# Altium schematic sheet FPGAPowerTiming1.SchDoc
size C
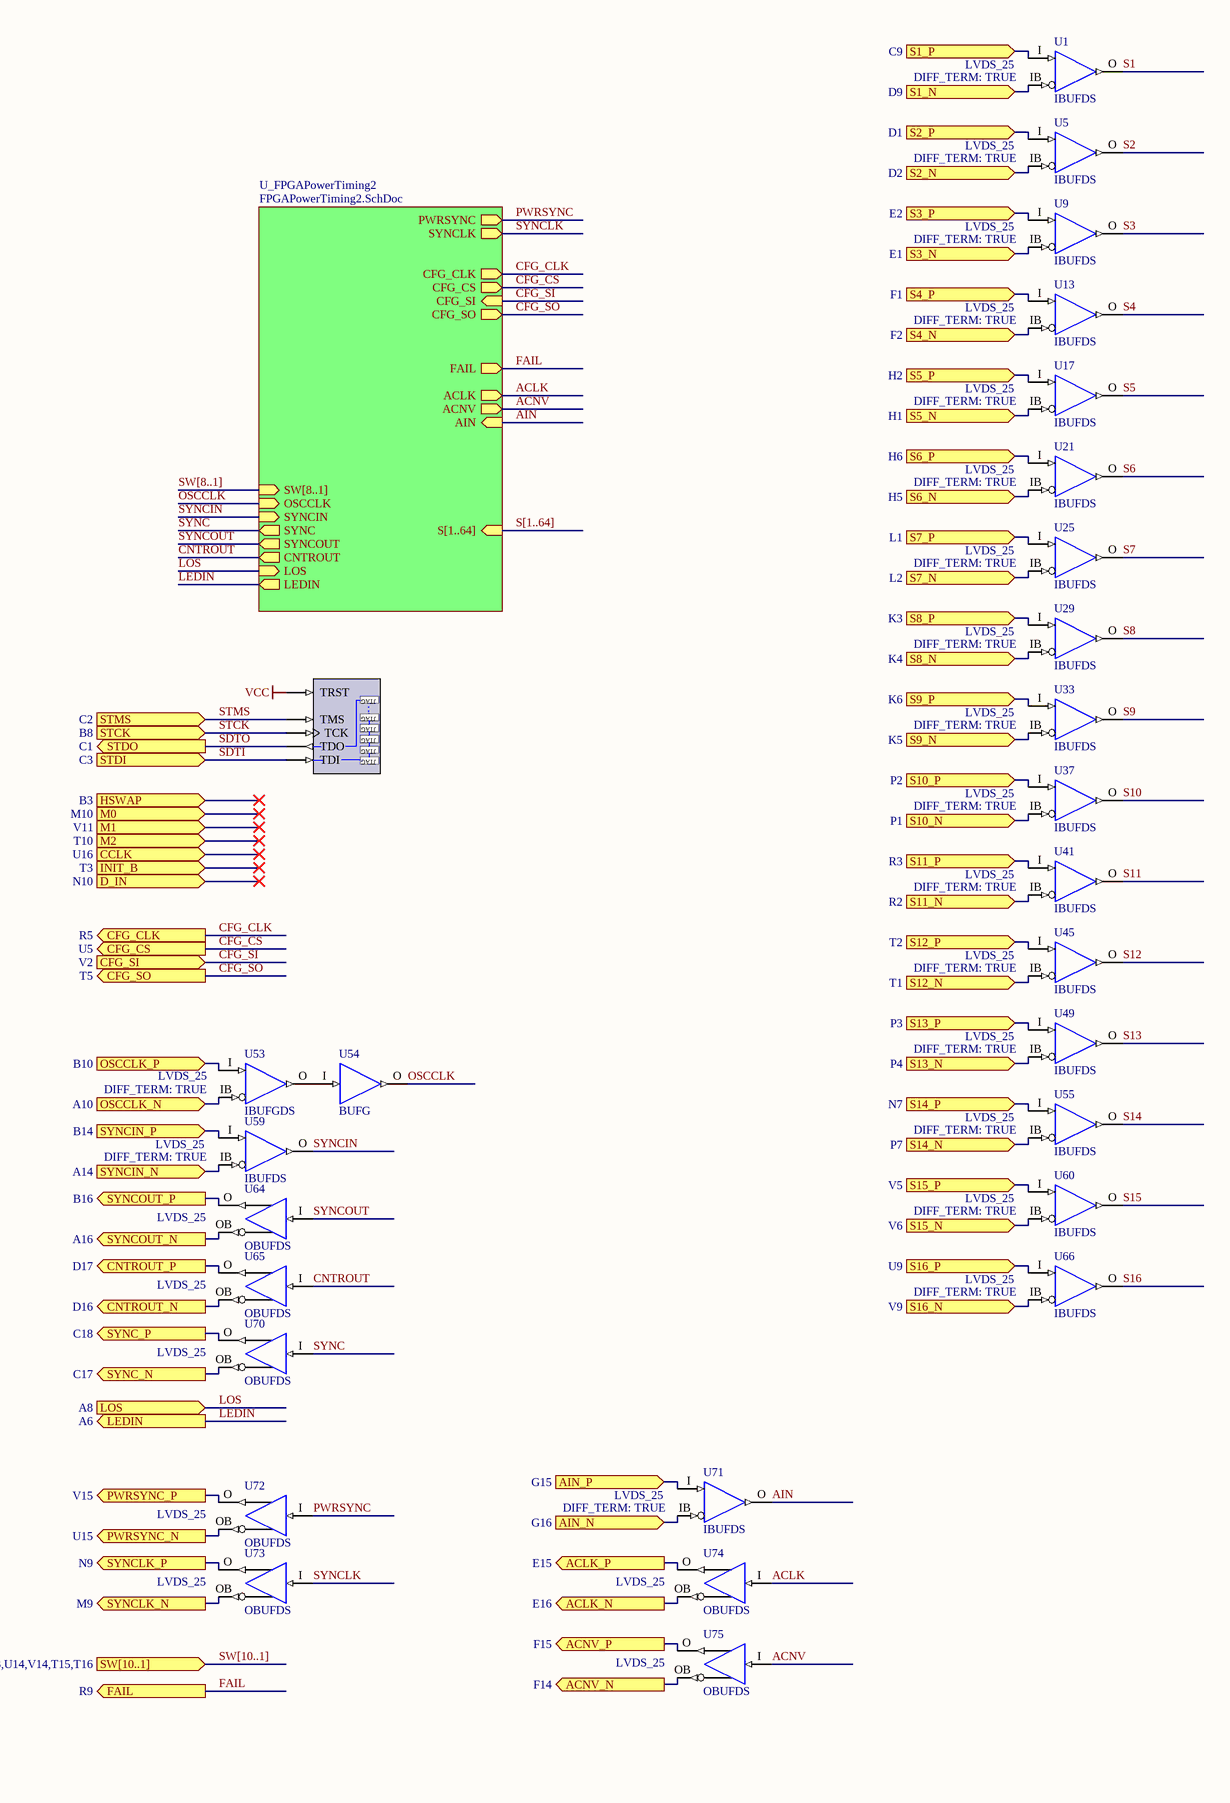
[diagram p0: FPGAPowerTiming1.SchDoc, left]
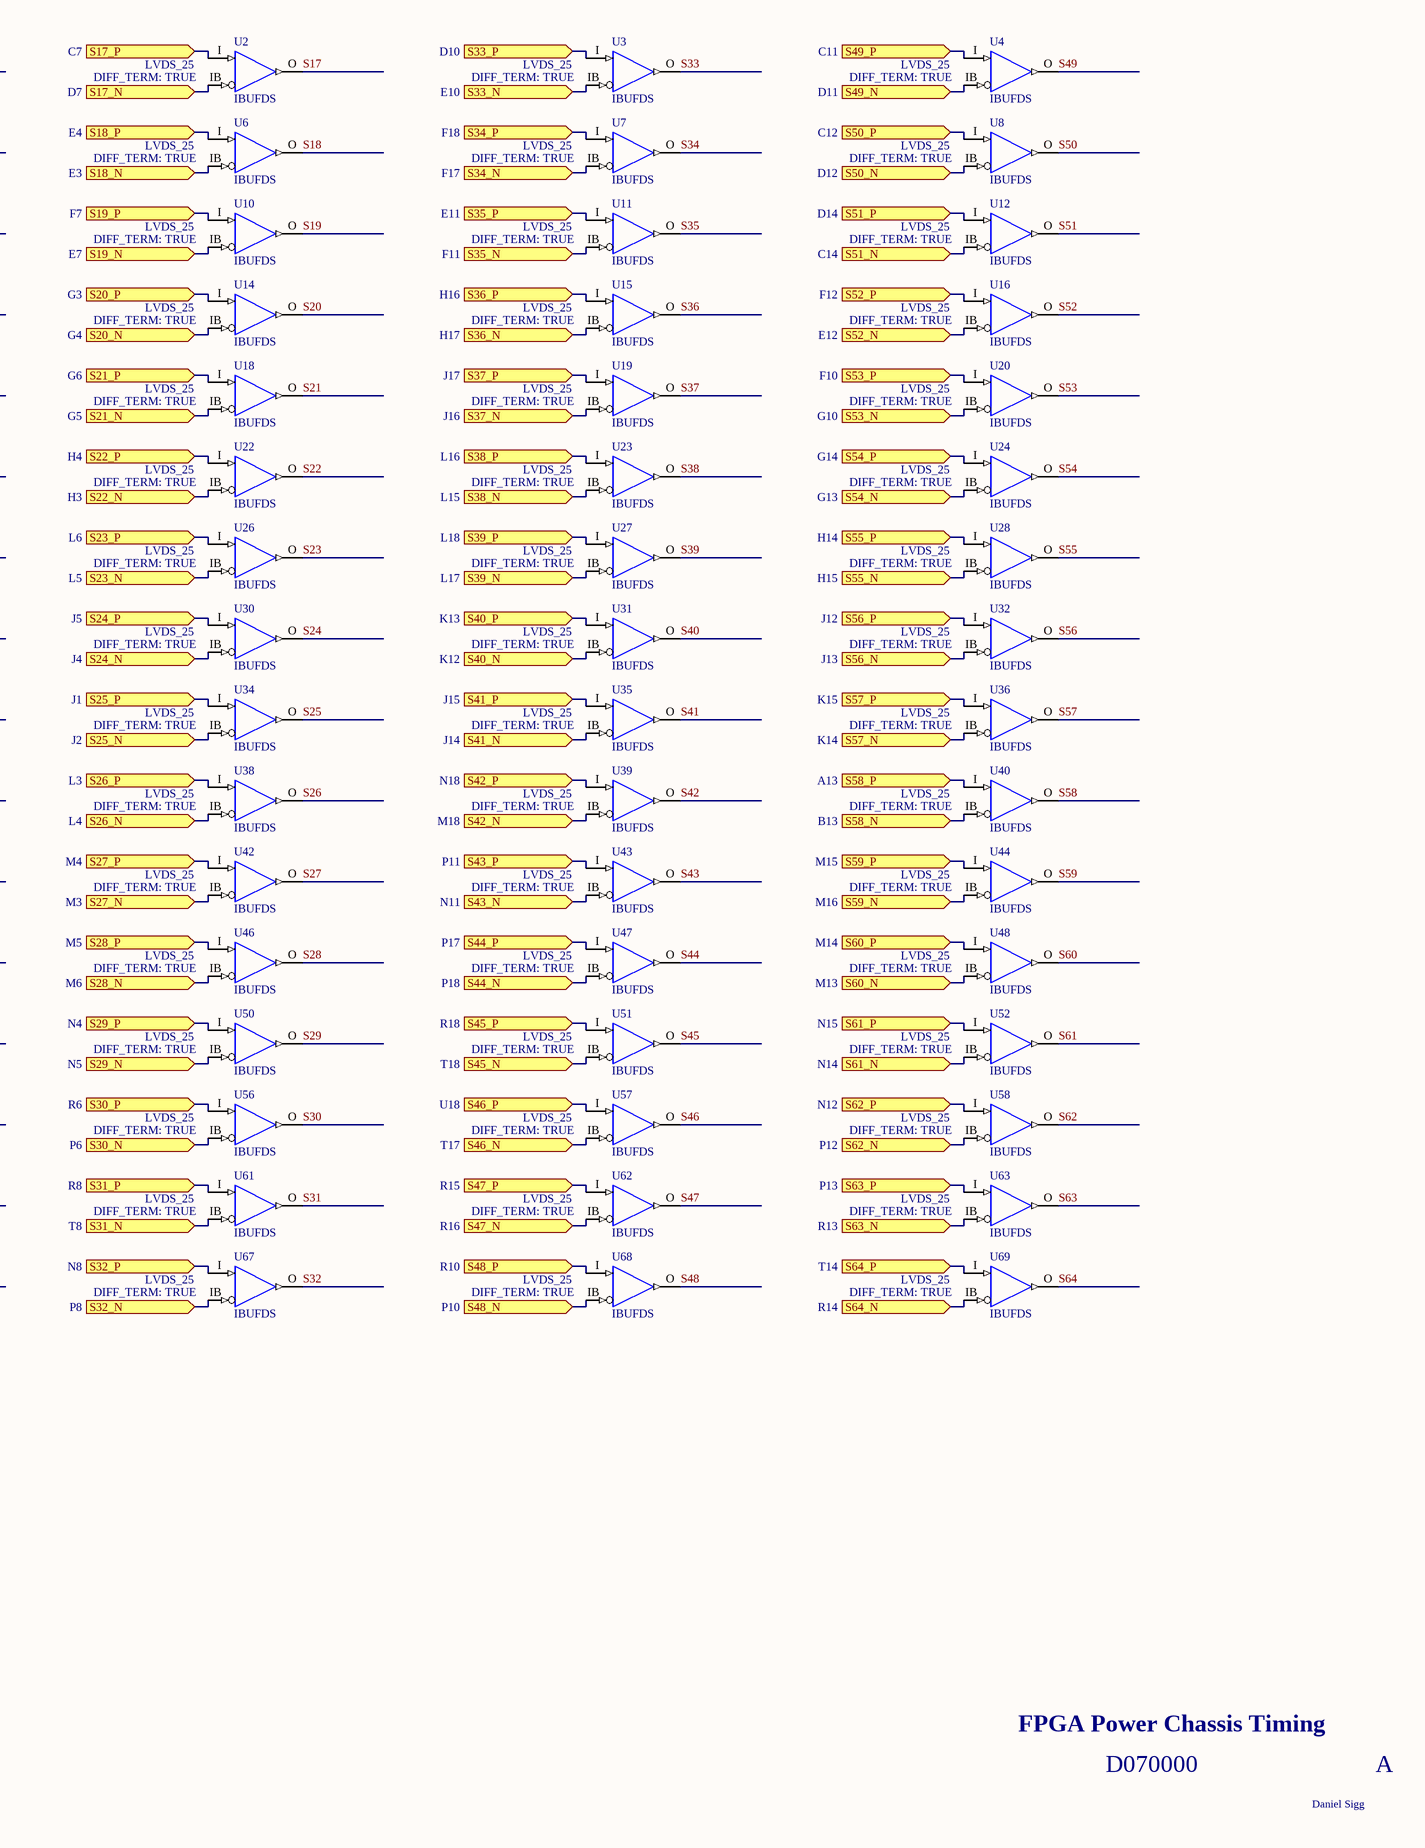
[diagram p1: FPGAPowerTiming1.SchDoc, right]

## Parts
NEXUS_JTAG_PORT  NEXUS_JTAG_PORT  (value not drawn)
U1  IBUFDS  IOSTANDARD: LVDS_25  DIFF_TERM: TRUE
U2  IBUFDS  IOSTANDARD: LVDS_25  DIFF_TERM: TRUE
U3  IBUFDS  IOSTANDARD: LVDS_25  DIFF_TERM: TRUE
U4  IBUFDS  IOSTANDARD: LVDS_25  DIFF_TERM: TRUE
U5  IBUFDS  IOSTANDARD: LVDS_25  DIFF_TERM: TRUE
U6  IBUFDS  IOSTANDARD: LVDS_25  DIFF_TERM: TRUE
U7  IBUFDS  IOSTANDARD: LVDS_25  DIFF_TERM: TRUE
U8  IBUFDS  IOSTANDARD: LVDS_25  DIFF_TERM: TRUE
U9  IBUFDS  IOSTANDARD: LVDS_25  DIFF_TERM: TRUE
U10  IBUFDS  IOSTANDARD: LVDS_25  DIFF_TERM: TRUE
U11  IBUFDS  IOSTANDARD: LVDS_25  DIFF_TERM: TRUE
U12  IBUFDS  IOSTANDARD: LVDS_25  DIFF_TERM: TRUE
U13  IBUFDS  IOSTANDARD: LVDS_25  DIFF_TERM: TRUE
U14  IBUFDS  IOSTANDARD: LVDS_25  DIFF_TERM: TRUE
U15  IBUFDS  IOSTANDARD: LVDS_25  DIFF_TERM: TRUE
U16  IBUFDS  IOSTANDARD: LVDS_25  DIFF_TERM: TRUE
U17  IBUFDS  IOSTANDARD: LVDS_25  DIFF_TERM: TRUE
U18  IBUFDS  IOSTANDARD: LVDS_25  DIFF_TERM: TRUE
U19  IBUFDS  IOSTANDARD: LVDS_25  DIFF_TERM: TRUE
U20  IBUFDS  IOSTANDARD: LVDS_25  DIFF_TERM: TRUE
U21  IBUFDS  IOSTANDARD: LVDS_25  DIFF_TERM: TRUE
U22  IBUFDS  IOSTANDARD: LVDS_25  DIFF_TERM: TRUE
U23  IBUFDS  IOSTANDARD: LVDS_25  DIFF_TERM: TRUE
U24  IBUFDS  IOSTANDARD: LVDS_25  DIFF_TERM: TRUE
U25  IBUFDS  IOSTANDARD: LVDS_25  DIFF_TERM: TRUE
U26  IBUFDS  IOSTANDARD: LVDS_25  DIFF_TERM: TRUE
U27  IBUFDS  IOSTANDARD: LVDS_25  DIFF_TERM: TRUE
U28  IBUFDS  IOSTANDARD: LVDS_25  DIFF_TERM: TRUE
U29  IBUFDS  IOSTANDARD: LVDS_25  DIFF_TERM: TRUE
U30  IBUFDS  IOSTANDARD: LVDS_25  DIFF_TERM: TRUE
U31  IBUFDS  IOSTANDARD: LVDS_25  DIFF_TERM: TRUE
U32  IBUFDS  IOSTANDARD: LVDS_25  DIFF_TERM: TRUE
U33  IBUFDS  IOSTANDARD: LVDS_25  DIFF_TERM: TRUE
U34  IBUFDS  IOSTANDARD: LVDS_25  DIFF_TERM: TRUE
U35  IBUFDS  IOSTANDARD: LVDS_25  DIFF_TERM: TRUE
U36  IBUFDS  IOSTANDARD: LVDS_25  DIFF_TERM: TRUE
U37  IBUFDS  IOSTANDARD: LVDS_25  DIFF_TERM: TRUE
U38  IBUFDS  IOSTANDARD: LVDS_25  DIFF_TERM: TRUE
U39  IBUFDS  IOSTANDARD: LVDS_25  DIFF_TERM: TRUE
U40  IBUFDS  IOSTANDARD: LVDS_25  DIFF_TERM: TRUE
U41  IBUFDS  IOSTANDARD: LVDS_25  DIFF_TERM: TRUE
U42  IBUFDS  IOSTANDARD: LVDS_25  DIFF_TERM: TRUE
U43  IBUFDS  IOSTANDARD: LVDS_25  DIFF_TERM: TRUE
U44  IBUFDS  IOSTANDARD: LVDS_25  DIFF_TERM: TRUE
U45  IBUFDS  IOSTANDARD: LVDS_25  DIFF_TERM: TRUE
U46  IBUFDS  IOSTANDARD: LVDS_25  DIFF_TERM: TRUE
U47  IBUFDS  IOSTANDARD: LVDS_25  DIFF_TERM: TRUE
U48  IBUFDS  IOSTANDARD: LVDS_25  DIFF_TERM: TRUE
U49  IBUFDS  IOSTANDARD: LVDS_25  DIFF_TERM: TRUE
U50  IBUFDS  IOSTANDARD: LVDS_25  DIFF_TERM: TRUE
U51  IBUFDS  IOSTANDARD: LVDS_25  DIFF_TERM: TRUE
U52  IBUFDS  IOSTANDARD: LVDS_25  DIFF_TERM: TRUE
U53  IBUFGDS  IOSTANDARD: LVDS_25  DIFF_TERM: TRUE
U54  BUFG
U55  IBUFDS  IOSTANDARD: LVDS_25  DIFF_TERM: TRUE
U56  IBUFDS  IOSTANDARD: LVDS_25  DIFF_TERM: TRUE
U57  IBUFDS  IOSTANDARD: LVDS_25  DIFF_TERM: TRUE
U58  IBUFDS  IOSTANDARD: LVDS_25  DIFF_TERM: TRUE
U59  IBUFDS  IOSTANDARD: LVDS_25  DIFF_TERM: TRUE
U60  IBUFDS  IOSTANDARD: LVDS_25  DIFF_TERM: TRUE
U61  IBUFDS  IOSTANDARD: LVDS_25  DIFF_TERM: TRUE
U62  IBUFDS  IOSTANDARD: LVDS_25  DIFF_TERM: TRUE
U63  IBUFDS  IOSTANDARD: LVDS_25  DIFF_TERM: TRUE
U64  OBUFDS  IOSTANDARD: LVDS_25
U65  OBUFDS  IOSTANDARD: LVDS_25
U66  IBUFDS  IOSTANDARD: LVDS_25  DIFF_TERM: TRUE
U67  IBUFDS  IOSTANDARD: LVDS_25  DIFF_TERM: TRUE
U68  IBUFDS  IOSTANDARD: LVDS_25  DIFF_TERM: TRUE
U69  IBUFDS  IOSTANDARD: LVDS_25  DIFF_TERM: TRUE
U70  OBUFDS  IOSTANDARD: LVDS_25
U71  IBUFDS  IOSTANDARD: LVDS_25  DIFF_TERM: TRUE
U72  OBUFDS  IOSTANDARD: LVDS_25
U73  OBUFDS  IOSTANDARD: LVDS_25
U74  OBUFDS  IOSTANDARD: LVDS_25
U75  OBUFDS  IOSTANDARD: LVDS_25

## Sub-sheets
U_FPGAPowerTiming2 = FPGAPowerTiming2.SchDoc: SW[8..1] (in), OSCCLK (in), SYNCIN (in), SYNCOUT (out), CNTROUT (out), SYNC (out), PWRSYNC (out), SYNCLK (out), LOS (in), LEDIN (out), CFG_CLK (out), CFG_CS (out), CFG_SO (out), CFG_SI (in), FAIL (out), ACLK (out), ACNV (out), AIN (in), S[1..64] (in)

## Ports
ACLK_N (out, see E16), ACLK_P (out, see E15), ACNV_N (out, see F14), ACNV_P (out, see F15), AIN_N (in, see G16), AIN_P (in, see G15), CCLK (in, see U16), CFG_CLK (out, see R5), CFG_CS (out, see U5), CFG_SI (in, see V2), CFG_SO (out, see T5), CNTROUT_N (out, see D16), CNTROUT_P (out, see D17), D_IN (in, see N10), FAIL (out, see R9), HSWAP (in, see B3), INIT_B (in, see T3), LEDIN (out, see A6), LOS (in, see A8), M0 (in, see M10), M1 (in, see V11), M2 (in, see T10), OSCCLK_N (in, see A10), OSCCLK_P (in, see B10), PWRSYNC_N (out, see U15), PWRSYNC_P (out, see V15), S1_N (in, see D9), S1_P (in, see C9), S2_N (in, see D2), S2_P (in, see D1), S3_N (in, see E1), S3_P (in, see E2), S4_N (in, see F2), S4_P (in, see F1), S5_N (in, see H1), S5_P (in, see H2), S6_N (in, see H5), S6_P (in, see H6), S7_N (in, see L2), S7_P (in, see L1), S8_N (in, see K4), S8_P (in, see K3), S9_N (in, see K5), S9_P (in, see K6), S10_N (in, see P1), S10_P (in, see P2), S11_N (in, see R2), S11_P (in, see R3), S12_N (in, see T1), S12_P (in, see T2), S13_N (in, see P4), S13_P (in, see P3), S14_N (in, see P7), S14_P (in, see N7), S15_N (in, see V6), S15_P (in, see V5), S16_N (in, see V9), S16_P (in, see U9), S17_N (in, see D7), S17_P (in, see C7), S18_N (in, see E3), S18_P (in, see E4), S19_N (in, see E7), S19_P (in, see F7), S20_N (in, see G4), S20_P (in, see G3), S21_N (in, see G5), S21_P (in, see G6), S22_N (in, see H3), S22_P (in, see H4), S23_N (in, see L5), S23_P (in, see L6), S24_N (in, see J4), S24_P (in, see J5), S25_N (in, see J2), S25_P (in, see J1), S26_N (in, see L4), S26_P (in, see L3), S27_N (in, see M3), S27_P (in, see M4), S28_N (in, see M6), S28_P (in, see M5), S29_N (in, see N5), S29_P (in, see N4), S30_N (in, see P6), S30_P (in, see R6), S31_N (in, see T8), S31_P (in, see R8), S32_N (in, see P8), S32_P (in, see N8), S33_N (in, see E10), S33_P (in, see D10), S34_N (in, see F17), S34_P (in, see F18), S35_N (in, see F11), S35_P (in, see E11), S36_N (in, see H17), S36_P (in, see H16), S37_N (in, see J16), S37_P (in, see J17), S38_N (in, see L15), S38_P (in, see L16), S39_N (in, see L17), S39_P (in, see L18), S40_N (in, see K12), S40_P (in, see K13), S41_N (in, see J14), S41_P (in, see J15), S42_N (in, see M18), S42_P (in, see N18), S43_N (in, see N11), S43_P (in, see P11), S44_N (in, see P18), S44_P (in, see P17), S45_N (in, see T18), S45_P (in, see R18), S46_N (in, see T17), S46_P (in, see U18), S47_N (in, see R16), S47_P (in, see R15), S48_N (in, see P10), S48_P (in, see R10), S49_N (in, see D11), S49_P (in, see C11), S50_N (in, see D12), S50_P (in, see C12), S51_N (in, see C14), S51_P (in, see D14), S52_N (in, see E12), S52_P (in, see F12), S53_N (in, see G10), S53_P (in, see F10), S54_N (in, see G13), S54_P (in, see G14), S55_N (in, see H15), S55_P (in, see H14), S56_N (in, see J13), S56_P (in, see J12), S57_N (in, see K14), S57_P (in, see K15), S58_N (in, see B13), S58_P (in, see A13), S59_N (in, see M16), S59_P (in, see M15), S60_N (in, see M13), S60_P (in, see M14), S61_N (in, see N14), S61_P (in, see N15), S62_N (in, see P12), S62_P (in, see N12), S63_N (in, see R13), S63_P (in, see P13), S64_N (in, see R14), S64_P (in, see T14), STCK (in, see B8), STDI (in, see C3), STDO (out, see C1), STMS (in, see C2), SW[10..1] (in, see D5,C4,V12,T12,R12,V13,U14,V14,T15,T16), SYNC_N (out, see C17), SYNC_P (out, see C18), SYNCIN_N (in, see A14), SYNCIN_P (in, see B14), SYNCLK_N (out, see M9), SYNCLK_P (out, see N9), SYNCOUT_N (out, see A16), SYNCOUT_P (out, see B16)

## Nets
VCC: NEXUS_JTAG_PORT.TRST
ACLK: U74.I ; sheet U_FPGAPowerTiming2/ACLK
ACLK_N: U74.OB ; port ACLK_N
ACLK_P: U74.O ; port ACLK_P
ACNV: U75.I ; sheet U_FPGAPowerTiming2/ACNV
ACNV_N: U75.OB ; port ACNV_N
ACNV_P: U75.O ; port ACNV_P
AIN: U71.O ; sheet U_FPGAPowerTiming2/AIN
AIN_N: U71.IB ; port AIN_N
AIN_P: U71.I ; port AIN_P
CFG_CLK: port CFG_CLK, sheet U_FPGAPowerTiming2/CFG_CLK
CFG_CS: port CFG_CS, sheet U_FPGAPowerTiming2/CFG_CS
CFG_SI: port CFG_SI, sheet U_FPGAPowerTiming2/CFG_SI
CFG_SO: port CFG_SO, sheet U_FPGAPowerTiming2/CFG_SO
CNTROUT: U65.I ; sheet U_FPGAPowerTiming2/CNTROUT
CNTROUT_N: U65.OB ; port CNTROUT_N
CNTROUT_P: U65.O ; port CNTROUT_P
FAIL: port FAIL, sheet U_FPGAPowerTiming2/FAIL
LEDIN: port LEDIN, sheet U_FPGAPowerTiming2/LEDIN
LOS: port LOS, sheet U_FPGAPowerTiming2/LOS
OSCCLK: U54.O ; sheet U_FPGAPowerTiming2/OSCCLK
OSCCLK_N: U53.IB ; port OSCCLK_N
OSCCLK_P: U53.I ; port OSCCLK_P
PWRSYNC: U72.I ; sheet U_FPGAPowerTiming2/PWRSYNC
PWRSYNC_N: U72.OB ; port PWRSYNC_N
PWRSYNC_P: U72.O ; port PWRSYNC_P
S1: U1.O
S1_N: U1.IB ; port S1_N
S1_P: U1.I ; port S1_P
S2: U5.O
S2_N: U5.IB ; port S2_N
S2_P: U5.I ; port S2_P
S3: U9.O
S3_N: U9.IB ; port S3_N
S3_P: U9.I ; port S3_P
S4: U13.O
S4_N: U13.IB ; port S4_N
S4_P: U13.I ; port S4_P
S5: U17.O
S5_N: U17.IB ; port S5_N
S5_P: U17.I ; port S5_P
S6: U21.O
S6_N: U21.IB ; port S6_N
S6_P: U21.I ; port S6_P
S7: U25.O
S7_N: U25.IB ; port S7_N
S7_P: U25.I ; port S7_P
S8: U29.O
S8_N: U29.IB ; port S8_N
S8_P: U29.I ; port S8_P
S9: U33.O
S9_N: U33.IB ; port S9_N
S9_P: U33.I ; port S9_P
S10: U37.O
S10_N: U37.IB ; port S10_N
S10_P: U37.I ; port S10_P
S11: U41.O
S11_N: U41.IB ; port S11_N
S11_P: U41.I ; port S11_P
S12: U45.O
S12_N: U45.IB ; port S12_N
S12_P: U45.I ; port S12_P
S13: U49.O
S13_N: U49.IB ; port S13_N
S13_P: U49.I ; port S13_P
S14: U55.O
S14_N: U55.IB ; port S14_N
S14_P: U55.I ; port S14_P
S15: U60.O
S15_N: U60.IB ; port S15_N
S15_P: U60.I ; port S15_P
S16: U66.O
S16_N: U66.IB ; port S16_N
S16_P: U66.I ; port S16_P
S17: U2.O
S17_N: U2.IB ; port S17_N
S17_P: U2.I ; port S17_P
S18: U6.O
S18_N: U6.IB ; port S18_N
S18_P: U6.I ; port S18_P
S19: U10.O
S19_N: U10.IB ; port S19_N
S19_P: U10.I ; port S19_P
S20: U14.O
S20_N: U14.IB ; port S20_N
S20_P: U14.I ; port S20_P
S21: U18.O
S21_N: U18.IB ; port S21_N
S21_P: U18.I ; port S21_P
S22: U22.O
S22_N: U22.IB ; port S22_N
S22_P: U22.I ; port S22_P
S23: U26.O
S23_N: U26.IB ; port S23_N
S23_P: U26.I ; port S23_P
S24: U30.O
S24_N: U30.IB ; port S24_N
S24_P: U30.I ; port S24_P
S25: U34.O
S25_N: U34.IB ; port S25_N
S25_P: U34.I ; port S25_P
S26: U38.O
S26_N: U38.IB ; port S26_N
S26_P: U38.I ; port S26_P
S27: U42.O
S27_N: U42.IB ; port S27_N
S27_P: U42.I ; port S27_P
S28: U46.O
S28_N: U46.IB ; port S28_N
S28_P: U46.I ; port S28_P
S29: U50.O
S29_N: U50.IB ; port S29_N
S29_P: U50.I ; port S29_P
S30: U56.O
S30_N: U56.IB ; port S30_N
S30_P: U56.I ; port S30_P
S31: U61.O
S31_N: U61.IB ; port S31_N
S31_P: U61.I ; port S31_P
S32: U67.O
S32_N: U67.IB ; port S32_N
S32_P: U67.I ; port S32_P
S33: U3.O
S33_N: U3.IB ; port S33_N
S33_P: U3.I ; port S33_P
S34: U7.O
S34_N: U7.IB ; port S34_N
S34_P: U7.I ; port S34_P
S35: U11.O
S35_N: U11.IB ; port S35_N
S35_P: U11.I ; port S35_P
S36: U15.O
S36_N: U15.IB ; port S36_N
S36_P: U15.I ; port S36_P
S37: U19.O
S37_N: U19.IB ; port S37_N
S37_P: U19.I ; port S37_P
S38: U23.O
S38_N: U23.IB ; port S38_N
S38_P: U23.I ; port S38_P
S39: U27.O
S39_N: U27.IB ; port S39_N
S39_P: U27.I ; port S39_P
S40: U31.O
S40_N: U31.IB ; port S40_N
S40_P: U31.I ; port S40_P
S41: U35.O
S41_N: U35.IB ; port S41_N
S41_P: U35.I ; port S41_P
S42: U39.O
S42_N: U39.IB ; port S42_N
S42_P: U39.I ; port S42_P
S43: U43.O
S43_N: U43.IB ; port S43_N
S43_P: U43.I ; port S43_P
S44: U47.O
S44_N: U47.IB ; port S44_N
S44_P: U47.I ; port S44_P
S45: U51.O
S45_N: U51.IB ; port S45_N
S45_P: U51.I ; port S45_P
S46: U57.O
S46_N: U57.IB ; port S46_N
S46_P: U57.I ; port S46_P
S47: U62.O
S47_N: U62.IB ; port S47_N
S47_P: U62.I ; port S47_P
S48: U68.O
S48_N: U68.IB ; port S48_N
S48_P: U68.I ; port S48_P
S49: U4.O
S49_N: U4.IB ; port S49_N
S49_P: U4.I ; port S49_P
S50: U8.O
S50_N: U8.IB ; port S50_N
S50_P: U8.I ; port S50_P
S51: U12.O
S51_N: U12.IB ; port S51_N
S51_P: U12.I ; port S51_P
S52: U16.O
S52_N: U16.IB ; port S52_N
S52_P: U16.I ; port S52_P
S53: U20.O
S53_N: U20.IB ; port S53_N
S53_P: U20.I ; port S53_P
S54: U24.O
S54_N: U24.IB ; port S54_N
S54_P: U24.I ; port S54_P
S55: U28.O
S55_N: U28.IB ; port S55_N
S55_P: U28.I ; port S55_P
S56: U32.O
S56_N: U32.IB ; port S56_N
S56_P: U32.I ; port S56_P
S57: U36.O
S57_N: U36.IB ; port S57_N
S57_P: U36.I ; port S57_P
S58: U40.O
S58_N: U40.IB ; port S58_N
S58_P: U40.I ; port S58_P
S59: U44.O
S59_N: U44.IB ; port S59_N
S59_P: U44.I ; port S59_P
S60: U48.O
S60_N: U48.IB ; port S60_N
S60_P: U48.I ; port S60_P
S61: U52.O
S61_N: U52.IB ; port S61_N
S61_P: U52.I ; port S61_P
S62: U58.O
S62_N: U58.IB ; port S62_N
S62_P: U58.I ; port S62_P
S63: U63.O
S63_N: U63.IB ; port S63_N
S63_P: U63.I ; port S63_P
S64: U69.O
S64_N: U69.IB ; port S64_N
S64_P: U69.I ; port S64_P
SDTI: NEXUS_JTAG_PORT.TDI ; port STDI
SDTO: NEXUS_JTAG_PORT.TDO ; port STDO
STCK: NEXUS_JTAG_PORT.TCK ; port STCK
STMS: NEXUS_JTAG_PORT.TMS ; port STMS
SYNC: U70.I ; sheet U_FPGAPowerTiming2/SYNC
SYNC_N: U70.OB ; port SYNC_N
SYNC_P: U70.O ; port SYNC_P
SYNCIN: U59.O ; sheet U_FPGAPowerTiming2/SYNCIN
SYNCIN_N: U59.IB ; port SYNCIN_N
SYNCIN_P: U59.I ; port SYNCIN_P
SYNCLK: U73.I ; sheet U_FPGAPowerTiming2/SYNCLK
SYNCLK_N: U73.OB ; port SYNCLK_N
SYNCLK_P: U73.O ; port SYNCLK_P
SYNCOUT: U64.I ; sheet U_FPGAPowerTiming2/SYNCOUT
SYNCOUT_N: U64.OB ; port SYNCOUT_N
SYNCOUT_P: U64.O ; port SYNCOUT_P
NetU53_O: U53.O U54.I

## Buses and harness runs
bus S[1..64] = sheet U_FPGAPowerTiming2/S[1..64]
bus SW[8..1] = sheet U_FPGAPowerTiming2/SW[8..1]
bus SW[10..1] = port SW[10..1]

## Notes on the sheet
- FPGA Power Chassis Timing
- D070000
- Daniel Sigg
- A

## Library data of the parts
NEXUS_JTAG_PORT = NEXUS_JTAG_PORT: Soft Nexus-Chain Connector; NEXUS_JTAG_CONNECTOR: True; FunctionalClass: JTAG
U1-U52 U55-U63 U66-U69 U71 = IBUFDS: Differential Signaling Input Buffer with Selectable I/O Interface; FPGAVendor: Xilinx
U53 = IBUFGDS: Dedicated Differential Signaling Input Buffer with Selectable I/O Interface; FPGAVendor: Xilinx
U54 = BUFG: Global Clock Buffer; FPGAVendor: Xilinx
U64 U65 U70 U72-U75 = OBUFDS: Differential Signaling Output Buffer with Selectable I/O Interface; FPGAVendor: Xilinx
